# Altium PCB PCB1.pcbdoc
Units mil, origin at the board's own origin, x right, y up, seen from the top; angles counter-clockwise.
Board outline 8425 x 5110 mil, 2 copper layers (Top Layer, Bottom Layer); 7 components, 16 nets, 61 pads, 3 vias.
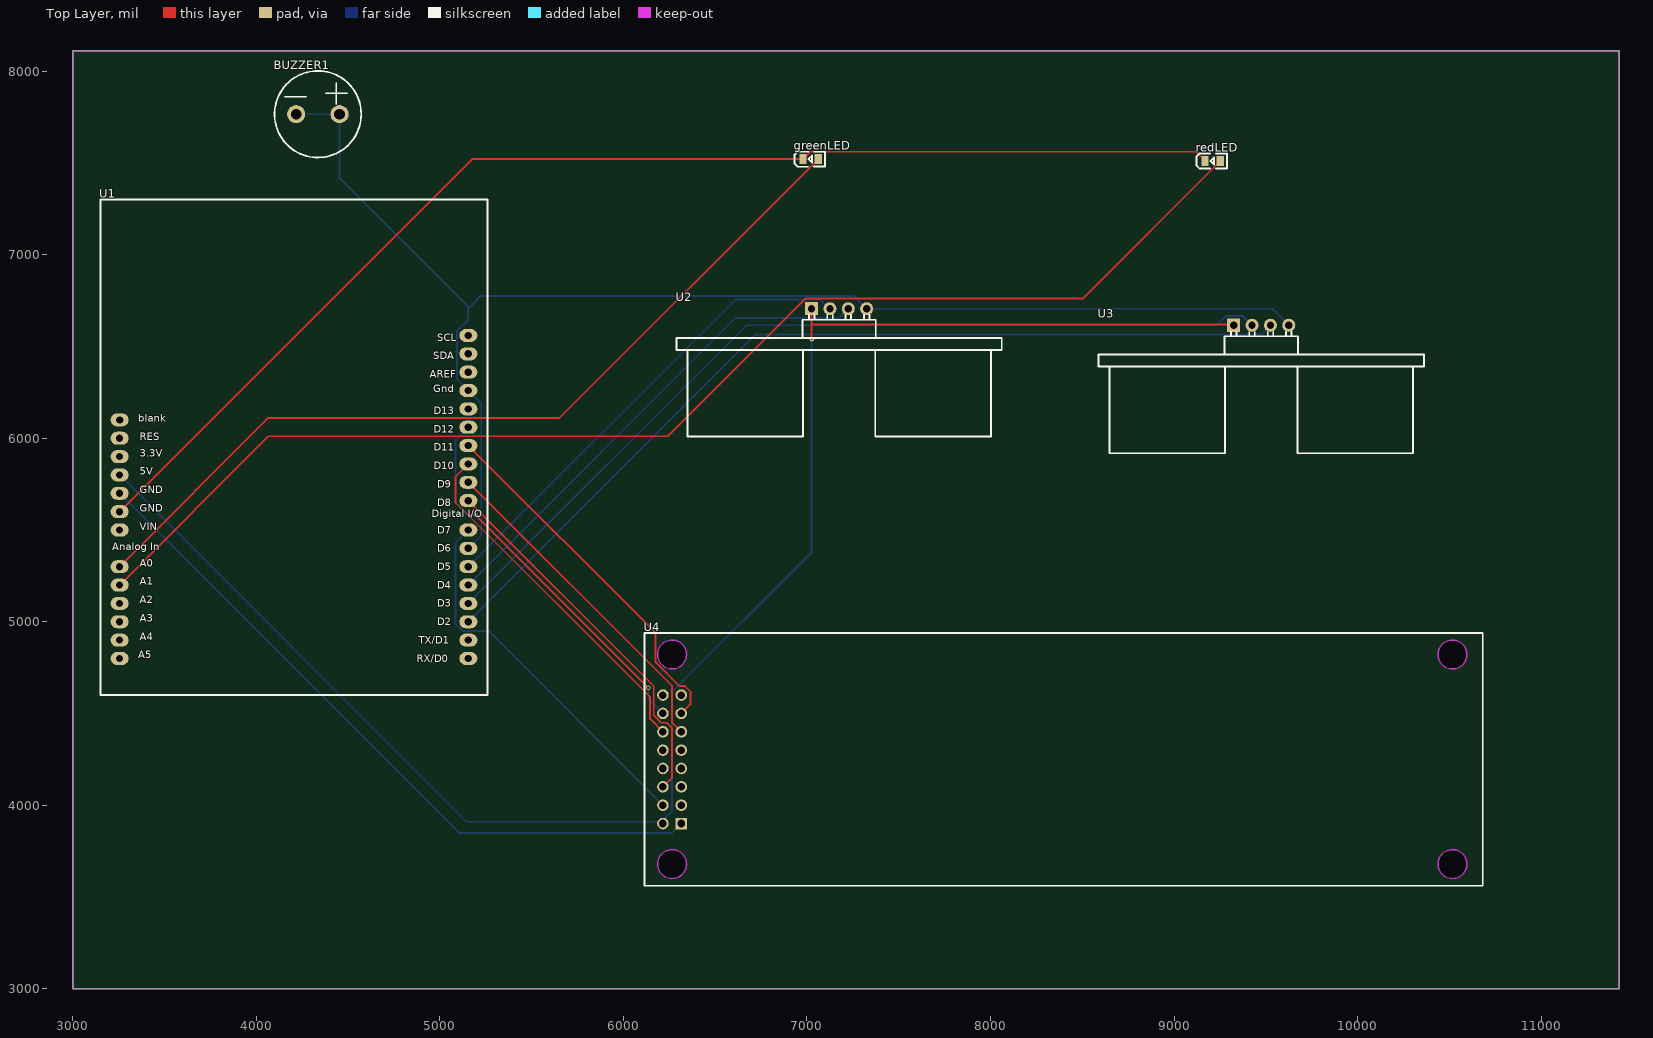
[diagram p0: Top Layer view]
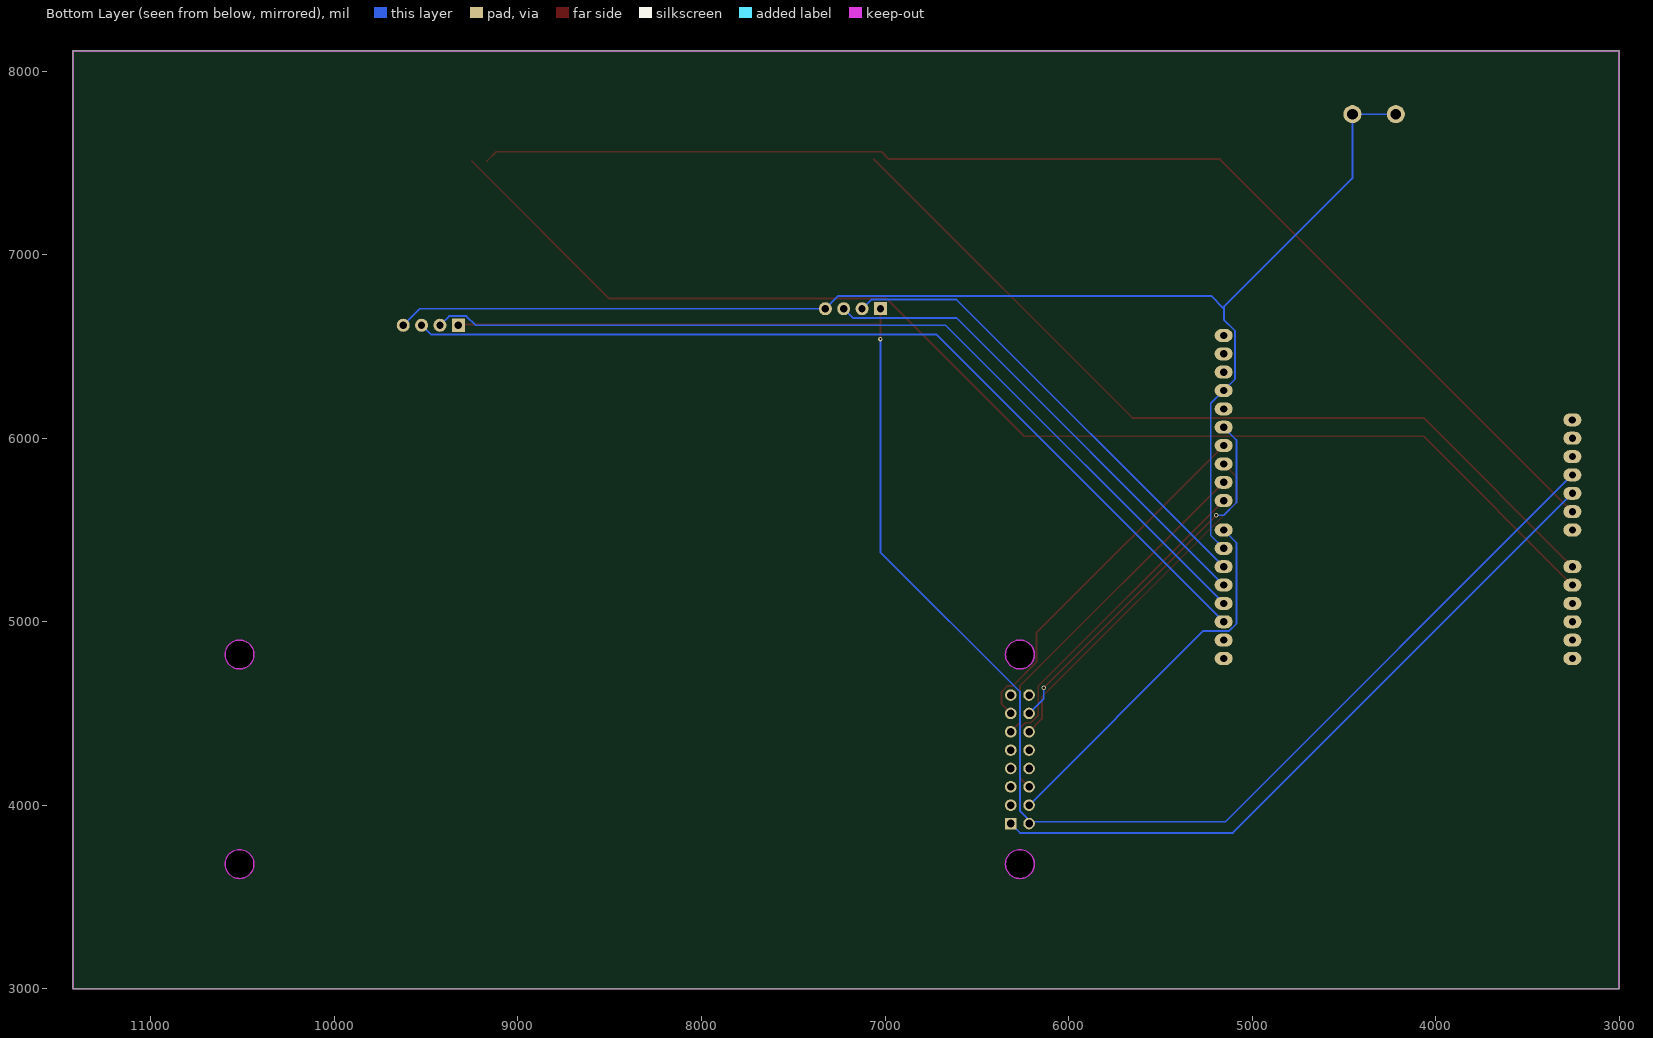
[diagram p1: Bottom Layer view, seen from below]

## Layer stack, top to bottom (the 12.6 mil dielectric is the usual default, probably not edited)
Top Layer: signal copper (thickness not stored)
Dielectric: dielectric 12.6, FR-4, Dk 4.8
Bottom Layer: signal copper (thickness not stored)

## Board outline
3000,8110 11425,8110 11425,3000 3000,3000

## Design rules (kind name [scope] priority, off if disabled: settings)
BoardOutlineClearance copperThickness1oz [All] p0: genericclearance=10 ignorepadtopadclearanceinfootprint=FALSE except(0: Arc-SplitContinuation Track-SplitContinuation SMDPad-SplitContinuation THPad-SplitContinuation Via-SplitContinuation Fill-SplitContinuation Poly-SplitContinuation Region-SplitContinuation Text-SplitContinuation; 6: Track-CutoutEdge SMDPad-CutoutEdge THPad-CutoutEdge Via-CutoutEdge Region-CutoutEdge; 11.8: Track-OutlineEdge SMDPad-OutlineEdge THPad-OutlineEdge Via-OutlineEdge Fill-OutlineEdge Region-OutlineEdge Poly-OutlineEdge Text-OutlineEdge Fill-CutoutEdge)
BoardOutlineClearance copperThickness2oz [All] p0: genericclearance=10 ignorepadtopadclearanceinfootprint=FALSE except(0: Arc-SplitContinuation Track-SplitContinuation SMDPad-SplitContinuation THPad-SplitContinuation Via-SplitContinuation Fill-SplitContinuation Poly-SplitContinuation Region-SplitContinuation Text-SplitContinuation; 6: Track-CutoutEdge SMDPad-CutoutEdge THPad-CutoutEdge Via-CutoutEdge Region-CutoutEdge; 11.8: Track-OutlineEdge SMDPad-OutlineEdge THPad-OutlineEdge Via-OutlineEdge Fill-OutlineEdge Region-OutlineEdge Poly-OutlineEdge Text-OutlineEdge Fill-CutoutEdge)
Clearance copperThickness1oz [(InNet('$1N2145') OR InNet('$1N2372') OR InNet('$1N2336') OR InNet('$1N2377') OR InNet('$1N2179') OR InNet('$1N2219') OR InNet('$1N2323') OR InNet('$1N2311') OR InNet('$1N2299') OR InNet('$1N2289') OR InNet('$1N2279') OR InNet('$1N2269') OR InNet('$1N2005') OR InNet('$1N2008') OR InNet('$1N2119') OR InNet('$1N2114'))] p1: gap=7 ignorepadtopadclearanceinfootprint=FALSE except(4: Track-Track; 6: Track-SMDPad SMDPad-SMDPad Track-THPad SMDPad-THPad THPad-THPad Track-Via SMDPad-Via THPad-Via Via-Via SMDPad-Fill THPad-Fill Via-Fill Fill-Fill Track-Region SMDPad-Region THPad-Region Via-Region Region-Region Track-Poly SMDPad-Poly THPad-Poly Via-Poly Fill-Poly Region-Poly Poly-Poly Track-Text SMDPad-Text THPad-Text Via-Text Fill-Text Region-Text Poly-Text Text-Text; 6.9: Track-Hole SMDPad-Hole THPad-Hole Via-Hole Fill-Hole Region-Hole Poly-Hole Text-Hole Sheet-Hole; 11.8: Track-Fill Fill-Region Track-Sheet SMDPad-Sheet THPad-Sheet Via-Sheet Fill-Sheet Region-Sheet Poly-Sheet Text-Sheet)
Clearance copperThickness2oz [All] p1: gap=7 ignorepadtopadclearanceinfootprint=FALSE except(6: Track-SMDPad SMDPad-SMDPad Track-THPad SMDPad-THPad THPad-THPad Track-Via SMDPad-Via THPad-Via Via-Via SMDPad-Fill THPad-Fill Via-Fill Fill-Fill Track-Region SMDPad-Region THPad-Region Via-Region Region-Region Track-Poly SMDPad-Poly THPad-Poly Via-Poly Fill-Poly Region-Poly Poly-Poly Track-Text SMDPad-Text THPad-Text Via-Text Fill-Text Region-Text Poly-Text Text-Text; 6.9: Track-Hole SMDPad-Hole THPad-Hole Via-Hole Fill-Hole Region-Hole Poly-Hole Text-Hole Sheet-Hole; 8: Track-Track; 11.8: Track-Fill Fill-Region Track-Sheet SMDPad-Sheet THPad-Sheet Via-Sheet Fill-Sheet Region-Sheet Poly-Sheet Text-Sheet)
DiffPairsRouting differentialPair [All] p1: maxuncoupledlength=10 minlimit=6 maxlimit=6 mostfreqgap=6 toplayer_minwidth=5 toplayer_prefwidth=10 toplayer_maxwidth=100 bottomlayer_minwidth=5 bottomlayer_prefwidth=10 bottomlayer_maxwidth=100
PasteMaskExpansion pasteMaskExpansion [All] p1: expansion=0
PlaneConnect innerPlane [All] p1: planeconnectstyle=Relief reliefexpansion=20 reliefentries=4 reliefconductorwidth=10 reliefairgap=10
PolygonConnect copperRegion [All] p1: connectstyle=Relief reliefentries=4 reliefconductorwidth=10 polygonreliefangle="90 Angle" airgapwidth=10
RoutingVias viaSize [All] p1: viastyle="Through Hole" holewidth=12.0078 minholewidth=11.811 maxholewidth=248.0314 width=24.0158 minwidth=19.685 maxwidth=393.7008
SolderMaskExpansion solderMaskExpansion [All] p1: useseparateexpansions=TRUE expansion=2 expansionbottom=2
Width copperThickness1oz [All] p1: maxlimit=100 minlimit=5 preferedwidth=10
Width copperThickness2oz [All] p1: maxlimit=100 minlimit=8 preferedwidth=10

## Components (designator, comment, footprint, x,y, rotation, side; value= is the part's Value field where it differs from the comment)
BUZZER1 "buzzer" BUZ-TH_BD12.0-P6.00-D0.9-RD 4335,7765 r0 top
greenLED "KT-0805G" LED0805-R-RD 7020,7520 r0 top
redLED "KT-0805G" LED0805-R-RD 9210,7510 r0 top
U1 "Arduino Uno" "ARDUINO UNO R3 FOOTPRINT" 3155,4600 r0 top
U2 "HC-SR04" TH_HC-SR04V 7175,6705 r0 top
U3 "HC-SR04" TH_HC-SR04V 9475,6615 r0 top
U4 "SMR16032-ZD" LCD-TH_SMR16032-ZD 6265,4250 r0 top

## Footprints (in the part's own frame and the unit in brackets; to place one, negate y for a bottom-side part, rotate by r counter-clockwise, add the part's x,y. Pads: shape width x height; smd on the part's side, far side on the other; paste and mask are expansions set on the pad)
"ARDUINO UNO R3 FOOTPRINT" [mm]
  oval 2.5x1.8 hole 1.001 copper offset -0.017,0: 1(2.551,38.085)
  oval 2.5x1.8 hole 1.001: 2(2.535,35.543) 3(2.535,33.003) 4(2.535,30.463) 5(2.535,27.923) 6(2.535,25.383) 7(2.535,22.843) 8(2.535,17.763) 9(2.535,15.223) 10(2.535,12.683) 11(2.535,10.143) 12(2.535,7.603) 13(2.535,5.063) 14(50.795,49.767) 15(50.795,47.227) 16(50.795,44.687) 17(50.795,42.147) 18(50.795,39.607) 19(50.795,37.067) 20(50.795,34.527) 21(50.795,31.987) 22(50.795,29.447) 23(50.795,26.907) 24(50.795,22.843) 25(50.795,20.303) 26(50.795,17.763) 27(50.795,15.223) 28(50.795,12.683) 29(50.795,10.143) 30(50.795,7.603) 31(50.795,5.063)
  silkscreen extent -0.13,0 53.47,68.58
BUZ-TH_BD12.0-P6.00-D0.9-RD [mm]
  round 2.5 hole 1.5: 1(-3,0) 2(3,0)
  silkscreen extent -5.99,-5.99 5.99,5.99
LCD-TH_SMR16032-ZD [mm]
  rect 1.6x1.6 hole 1.05: 1(1.27,-8.89)
  round 1.6 hole 1.05: 2(-1.27,-8.89) 3(1.27,-6.35) 4(-1.27,-6.35) 5(1.27,-3.81) 6(-1.27,-3.81) 7(1.27,-1.27) 8(-1.27,-1.27) 9(1.27,1.27) 10(-1.27,1.27) 11(1.27,3.81) 12(-1.27,3.81) 13(1.27,6.35) 14(-1.27,6.35) 15(1.27,8.89) 16(-1.27,8.89)
  Board Outline Layer circle w0.005: c0,14.5 r2
  Board Outline Layer circle w0.005: c0,-14.5 r2
  Board Outline Layer circle w0.005: c108,-14.5 r2
  Board Outline Layer circle w0.005: c108,14.5 r2
  Board Outline Layer region: 2,14.5 1.802,13.632 1.247,12.936 0.445,12.55 -0.445,12.55 -1.247,12.936 -1.802,13.632 -2,14.5 -2,14.5 -1.802,15.368 -1.247,16.064 -0.445,16.45 0.445,16.45 1.247,16.064 1.802,15.368 2,14.5
  Board Outline Layer region: 2,-14.5 1.802,-15.368 1.247,-16.064 0.445,-16.45 -0.445,-16.45 -1.247,-16.064 -1.802,-15.368 -2,-14.5 -2,-14.5 -1.802,-13.632 -1.247,-12.936 -0.445,-12.55 0.445,-12.55 1.247,-12.936 1.802,-13.632 2,-14.5
  Board Outline Layer region: 110,-14.5 109.802,-15.368 109.247,-16.064 108.445,-16.45 107.555,-16.45 106.753,-16.064 106.198,-15.368 106,-14.5 106,-14.5 106.198,-13.632 106.753,-12.936 107.555,-12.55 108.445,-12.55 109.247,-12.936 109.802,-13.632 110,-14.5
  Board Outline Layer region: 110,14.5 109.802,13.632 109.247,12.936 108.445,12.55 107.555,12.55 106.753,12.936 106.198,13.632 106,14.5 106,14.5 106.198,15.368 106.753,16.064 107.555,16.45 108.445,16.45 109.247,16.064 109.802,15.368 110,14.5
  Multi-Layer board cut-out: 2,14.5 1.802,13.632 1.247,12.936 0.445,12.55 -0.445,12.55 -1.247,12.936 -1.802,13.632 -2,14.5 -2,14.5 -1.802,15.368 -1.247,16.064 -0.445,16.45 0.445,16.45 1.247,16.064 1.802,15.368 2,14.5
  Multi-Layer board cut-out: 2,-14.5 1.802,-15.368 1.247,-16.064 0.445,-16.45 -0.445,-16.45 -1.247,-16.064 -1.802,-15.368 -2,-14.5 -2,-14.5 -1.802,-13.632 -1.247,-12.936 -0.445,-12.55 0.445,-12.55 1.247,-12.936 1.802,-13.632 2,-14.5
  Multi-Layer board cut-out: 110,-14.5 109.802,-15.368 109.247,-16.064 108.445,-16.45 107.555,-16.45 106.753,-16.064 106.198,-15.368 106,-14.5 106,-14.5 106.198,-13.632 106.753,-12.936 107.555,-12.55 108.445,-12.55 109.247,-12.936 109.802,-13.632 110,-14.5
  Multi-Layer board cut-out: 110,14.5 109.802,13.632 109.247,12.936 108.445,12.55 107.555,12.55 106.753,12.936 106.198,13.632 106,14.5 106,14.5 106.198,15.368 106.753,16.064 107.555,16.45 108.445,16.45 109.247,16.064 109.802,15.368 110,14.5
  silkscreen extent -3.81,-17.5 112.19,17.5
LED0805-R-RD [mm]
  rect 1x1.4 smd: 1(1.05,0) 2(-1.05,0)
  silkscreen extent -2.22,-1.04 1.99,1.01
TH_HC-SR04V [mm]
  rect 1.8x1.8 hole 1.001: 1(-3.81,0)
  round 1.8 hole 1.001: 2(-1.27,0) 3(1.27,0) 4(3.81,0)
  silkscreen extent -22.5,-17.7 22.5,-0.89

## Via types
v1: diameter 24.02, hole 12.01, Top Layer to Bottom Layer, 3 vias

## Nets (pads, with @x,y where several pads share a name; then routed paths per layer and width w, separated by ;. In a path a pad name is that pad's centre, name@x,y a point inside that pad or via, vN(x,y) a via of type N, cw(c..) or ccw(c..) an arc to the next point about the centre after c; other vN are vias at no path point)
$1N2005: U1.26 U2.2 | length 2593.9
  Bottom Layer w10: U1.26 6610.45,6755 7075,6755 U2.2
$1N2008: U1.27 U2.3 | length 2693.9
  Bottom Layer w10: U1.27 6610.45,6655 7175,6655 U2.3
$1N2114: U1.29 U3.3 | length 5039.4
  Bottom Layer w10: U1.29 6720.78,6565.33 9475.33,6565.33 U3.3
$1N2119: U1.28 U3.2 | length 4939.4
  Bottom Layer w10: U1.28 6670.45,6615 9230.45,6615 9280.45,6665 9375,6665 U3.2
$1N2145: BUZZER1.1 BUZZER1.2 U1.17 U1.25 U2.4 U3.4 | length 7567.4
  Bottom Layer w10: BUZZER1.1 BUZZER1.2 4453.11,7415 5153.11,6715 5153.11,6705 ; U1.25 5224.8,5469.35 5224.8,6189.35 U1.17 5093.11,6321.04 5093.11,6585 5153.11,6645 5153.11,6705 ; U3.4 9535,6705 U2.4 7255,6775 5223.11,6775 5153.11,6705
$1N2179: U1.4 U2.1 U3.1 U4.2 | length 9183.8
  Top Layer w10: v1(7024.8,6539.35) 7024.8,6619.35 ; U2.1@7024.8,6704.8 7024.8,6619.35 ; U3.1 9320.65,6619.35 7024.8,6619.35
  Bottom Layer w10: U1.4 5144.8,3909.35 U4.2@6204.8,3909.35 ; U4.2 U4.2@6204.8,3909.35 ; v1(7024.8,6539.35) 7024.8,5379.35 6264.8,4619.35 6264.8,3969.35 U4.2@6204.8,3909.35
$1N2219: U1.5 U4.1 | length 3847.5
  Bottom Layer w10: U1.5 5104.8,3849.35 6264.35,3849.35 U4.1
$1N2269: U1.24 U4.4 | length 2079
  Bottom Layer w10: U1.24 5084.8,5429.35 5084.8,4989.35 5124.8,4949.35 5265.65,4949.35 U4.4
$1N2279: U1.23 U4.6 | length 2057.3
  Top Layer w10: U1.23 6164.8,4649.35 6164.8,4489.35 6204.8,4449.35 6234.8,4449.35 6264.8,4419.35 6264.8,4149.8 U4.6
$1N2289: U1.22 U4.11 | length 1839.9
  Top Layer w10: U1.22 6264.8,4649.35 6264.8,4450.2 U4.11
$1N2299: U1.21 U4.12 | length 1956.5
  Top Layer w10: U1.21 5084.8,5789.35 5084.8,5649.35 6144.8,4589.35 6144.8,4470.2 U4.12
$1N2311: U1.20 U4.13 | length 1998.7
  Top Layer w10: U1.20 6174.8,4939.35 6174.8,4779.35 6304.8,4649.35 6334.8,4649.35 6364.8,4619.35 6364.8,4549.8 U4.13
$1N2323: U1.19 U4.14 | length 2079.9
  Top Layer w10: v1(5194.8,5579.35) v1(6134.8,4639.35)
  Bottom Layer w10: U1.19 5084.8,5989.35 5084.8,5649.35 5154.8,5579.35 v1(5194.8,5579.35) ; v1(6134.8,4639.35) 6134.8,4580.2 U4.14
$1N2336: greenLED.1 U1.8 | length 4726.4
  Top Layer w10: U1.8 4065.45,6110 5651.35,6110 greenLED.1
$1N2372: greenLED.2 redLED.2 U1.6 | length 6746.7
  Top Layer w10: U1.6 5175.45,7520 greenLED.2 7018.65,7560 9118.65,7560 redLED.2
$1N2377: redLED.1 U1.9 | length 6953.7
  Top Layer w10: U1.9 4065.45,6010 6241.35,6010 6991.35,6760 8501.35,6760 redLED.1
pads on no net: U1.1 U1.2 U1.3 U1.7 U1.10 U1.11 U1.12 U1.13 U1.14 U1.15 U1.16 U1.18 U1.30 U1.31 U4.3 U4.5 U4.7 U4.8 U4.9 U4.10 U4.15 U4.16

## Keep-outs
Board Outline Layer:
  the board outline again, w10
